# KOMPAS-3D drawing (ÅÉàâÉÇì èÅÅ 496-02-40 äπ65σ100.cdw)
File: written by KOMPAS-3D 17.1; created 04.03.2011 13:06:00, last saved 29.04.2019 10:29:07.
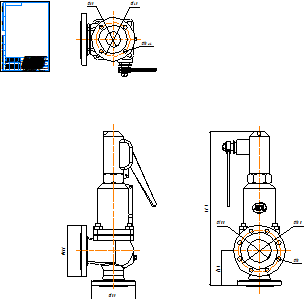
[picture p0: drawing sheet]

Sheet 1: A4, portrait

Title block, sheet 1: name: ПРЕГРАН КПП 496-02-40 / Ду65х100; material: Внимание! Данный продукт является объектом авторского права ООО «Торговый Дом АДЛ». / Запрещается изменение, копирование, распространение / (в том числе путем копирования на другие сайты и ресурсы в Интернете) / или любое иное использование информации и объектов без предварительного / согласия правообладателя (ООО «Торговый Дом АДЛ»).; scale: 1:1; sheets: 1; organisation: ООО "Торговый дом АДЛ"; sheet format: A4; stored path: C:\Users\tra\Desktop\2д чертежи\Предохранительные клапаны ПРЕГРАН\ПРЕГРАН 496\ПРЕГРАН КПП 496-02-40\KOMPAS 2D\ПРЕГРАН КПП 496-02-40 Ду65х100.cdw

Views: Спереди 1, Проекционный вид 2, Проекционный вид 3
Dimensions and other numbers on the sheet: 147; 657; 185; 220; 180; 18; 100; 145; 65; 1:1; 1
